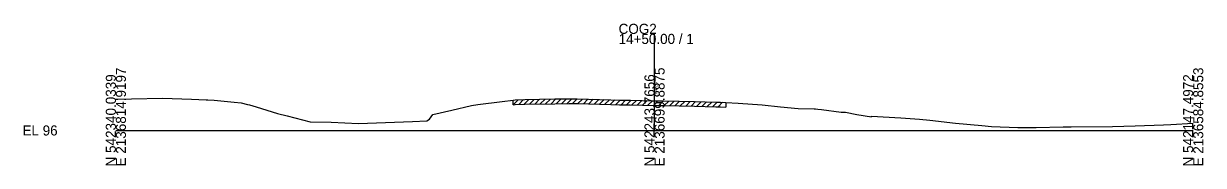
# Model space of a CAD drawing. Extents: x -13397 to 2303, y -10 to 39059.
# Drawn here: x -25.7 to 302.8, y 8990.3 to 9029.7 of the extents above; entities that cross this region are included whole.
import ezdxf

# ---------------------------------------------------------------- set-up
doc = ezdxf.new("R2010")
doc.units = 0
for name, color, linetype in [('RD_GPK_XS_Cell', 7, 'Continuous'), ('RD_XS_ExGround', 7, 'Continuous'), ('RD_XS_ExPaveRet', 7, 'Continuous'), ('RD_XS_TX_Elev_EX', 7, 'Continuous')]:
    doc.layers.add(name, color=color, linetype=linetype)

msp = doc.modelspace()

# ---------------------------------------------------------------- linework, layer by layer
at = {"layer": 'RD_GPK_XS_Cell'}
for p, q in [((150, 9000), (150, 9026.83)), ((0, 9000), (150, 9000)), ((150, 9000), (300, 9000))]:
    msp.add_line(p, q, dxfattribs=at)
at = {"layer": 'RD_XS_ExGround'}
for p, q in [((0, 9008.67), (0.59, 9008.69)), ((0.59, 9008.69), (4.37, 9008.76)), ((4.37, 9008.76), (12.98, 9008.94)), ((12.98, 9008.94), (21.05, 9008.66)), ((21.05, 9008.66), (25.11, 9008.52)), ((25.11, 9008.52), (25.61, 9008.5)), ((25.61, 9008.5), (27.41, 9008.45)), ((27.41, 9008.45), (32.94, 9007.9)), ((107.53, 9008.03), (110.68, 9008.44)), ((110.68, 9008.44), (111.17, 9008.47)), ((111.17, 9008.47), (113.88, 9008.57)), ((113.88, 9008.57), (122.21, 9008.74)), ((122.21, 9008.74), (126.2, 9008.81)), ((126.2, 9008.81), (128.41, 9008.76)), ((128.41, 9008.76), (137.8, 9008.53)), ((137.8, 9008.53), (140.29, 9008.45)), ((140.29, 9008.45), (140.71, 9008.44)), ((140.71, 9008.44), (143.2, 9008.4)), ((143.2, 9008.4), (150, 9008.26)), ((32.94, 9007.9), (34.91, 9007.63)), ((34.91, 9007.63), (36.65, 9007.24)), ((36.65, 9007.24), (37.19, 9007.15)), ((37.19, 9007.15), (39.07, 9006.57)), ((39.07, 9006.57), (44.99, 9004.75)), ((88.24, 9004.44), (93.58, 9005.68)), ((93.58, 9005.68), (99, 9006.91)), ((99, 9006.91), (100.82, 9007.24)), ((100.82, 9007.24), (107.53, 9008.03)), ((150, 9008.26), (152.62, 9008.2)), ((152.62, 9008.2), (161.17, 9008.01)), ((161.17, 9008.01), (167.04, 9007.87)), ((167.04, 9007.87), (168.41, 9007.85)), ((168.41, 9007.85), (169.88, 9007.8)), ((169.88, 9007.8), (173.26, 9007.55)), ((173.26, 9007.55), (179.95, 9007.1)), ((179.95, 9007.1), (185.11, 9006.55)), ((185.11, 9006.55), (189.95, 9006.09)), ((189.95, 9006.09), (194.41, 9006.01)), ((194.41, 9006.01), (194.85, 9006.01)), ((194.85, 9006.01), (195.46, 9005.9)), ((195.46, 9005.9), (196.49, 9005.83)), ((196.49, 9005.83), (201.99, 9005.04)), ((201.99, 9005.04), (203.16, 9005.12)), ((203.16, 9005.12), (206.3, 9004.45)), ((44.99, 9004.75), (47.67, 9004.06)), ((47.67, 9004.06), (54.14, 9002.37)), ((54.14, 9002.37), (60, 9002.29)), ((60, 9002.29), (67.54, 9001.96)), ((67.54, 9001.96), (82.58, 9002.53)), ((82.58, 9002.53), (86.63, 9002.68)), ((86.63, 9002.68), (87.3, 9003.15)), ((87.3, 9003.15), (88.24, 9004.44)), ((206.3, 9004.45), (210.39, 9003.8)), ((210.39, 9003.8), (210.4, 9003.96)), ((210.4, 9003.96), (218.55, 9003.48)), ((218.55, 9003.48), (223.8, 9003.13)), ((223.8, 9003.13), (226.65, 9002.86)), ((226.65, 9002.86), (233.8, 9001.99)), ((233.8, 9001.99), (241.12, 9001.39)), ((293.81, 9001.65), (300, 9002.03)), ((241.12, 9001.39), (243.8, 9001.1)), ((243.8, 9001.1), (251.15, 9000.85)), ((251.15, 9000.85), (256.3, 9000.79)), ((256.3, 9000.79), (263.8, 9000.99)), ((263.8, 9000.99), (266.01, 9001.03)), ((266.01, 9001.03), (277.55, 9001.13)), ((277.55, 9001.13), (283.81, 9001.3)), ((283.81, 9001.3), (291.71, 9001.57)), ((291.71, 9001.57), (293.81, 9001.65))]:
    msp.add_line(p, q, dxfattribs=at)
at = {"layer": 'RD_XS_ExPaveRet'}
for p, q in [((110.68, 9007.14), (112.04, 9008.5)), ((110.68, 9007.14), (110.68, 9008.44)), ((112.18, 9007.21), (113.53, 9008.56)), ((113.68, 9007.26), (115.01, 9008.59)), ((115.18, 9007.3), (116.51, 9008.62)), ((116.68, 9007.33), (118.01, 9008.65)), ((118.18, 9007.36), (119.51, 9008.68)), ((119.68, 9007.39), (121.01, 9008.72)), ((121.18, 9007.42), (122.51, 9008.75)), ((122.68, 9007.45), (124.01, 9008.77)), ((124.18, 9007.48), (125.51, 9008.8)), ((125.68, 9007.51), (126.97, 9008.8)), ((127.18, 9007.49), (128.45, 9008.76)), ((128.68, 9007.46), (129.95, 9008.73)), ((130.18, 9007.42), (131.45, 9008.69)), ((131.68, 9007.38), (132.95, 9008.65)), ((133.18, 9007.35), (134.45, 9008.61)), ((134.68, 9007.31), (135.95, 9008.58)), ((136.18, 9007.27), (137.45, 9008.54)), ((137.68, 9007.23), (138.94, 9008.49)), ((139.18, 9007.19), (140.44, 9008.45)), ((140.68, 9007.14), (141.96, 9008.42)), ((142.18, 9007.12), (143.46, 9008.39)), ((110.68, 9007.14), (111.17, 9007.17)), ((111.17, 9007.17), (113.88, 9007.27)), ((113.88, 9007.27), (122.21, 9007.44)), ((122.21, 9007.44), (126.2, 9007.51)), ((126.2, 9007.51), (128.41, 9007.46)), ((128.41, 9007.46), (137.8, 9007.23)), ((137.8, 9007.23), (140.29, 9007.15)), ((140.29, 9007.15), (140.71, 9007.14)), ((140.71, 9007.14), (143.2, 9007.1)), ((143.2, 9007.1), (150, 9006.96)), ((143.68, 9007.09), (144.96, 9008.36)), ((145.18, 9007.06), (146.46, 9008.33)), ((146.68, 9007.03), (147.96, 9008.3)), ((148.18, 9006.99), (149.46, 9008.27)), ((149.68, 9006.96), (150.96, 9008.23)), ((150, 9006.96), (152.62, 9006.9)), ((151.18, 9006.93), (152.46, 9008.2)), ((152.62, 9006.9), (161.17, 9006.71)), ((152.68, 9006.9), (153.95, 9008.17)), ((154.18, 9006.87), (155.45, 9008.14)), ((155.68, 9006.83), (156.95, 9008.11)), ((157.18, 9006.8), (158.45, 9008.07)), ((158.68, 9006.77), (159.95, 9008.04)), ((160.18, 9006.73), (161.45, 9008.01)), ((161.17, 9006.71), (167.04, 9006.57)), ((161.68, 9006.7), (162.95, 9007.97)), ((163.18, 9006.66), (164.45, 9007.93)), ((164.68, 9006.63), (165.95, 9007.9)), ((166.18, 9006.59), (167.45, 9007.86)), ((167.04, 9006.57), (168.41, 9006.55)), ((167.68, 9006.56), (168.95, 9007.83)), ((168.41, 9006.55), (169.88, 9006.5)), ((169.88, 9007.8), (169.88, 9006.5))]:
    msp.add_line(p, q, dxfattribs=at)

# ---------------------------------------------------------------- texts
at = {"layer": 'RD_GPK_XS_Cell'}
for s, p in [('COG2', (140, 9026.83)), ('14+50.00 / 1', (140, 9024.03)), ('EL 96', (-26, 8998.6))]:
    msp.add_text(s, height=2.8, dxfattribs=at).set_placement(p)
for s, p in [('N 542340.0339', (0, 8990)), ('E 2136814.9197', (2.8, 8990)), ('N 542243.7656', (150, 8990)), ('E 2136699.8875', (152.8, 8990)), ('N 542147.4972', (300, 8990)), ('E 2136584.8553', (302.8, 8990))]:
    msp.add_text(s, height=2.8, rotation=90, dxfattribs=at).set_placement(p)
at = {"layer": 'RD_XS_TX_Elev_EX'}
msp.add_text('104.26', height=1, rotation=90, dxfattribs=at).set_placement((150.75, 9009.26))

doc.saveas('drawing.dxf')
